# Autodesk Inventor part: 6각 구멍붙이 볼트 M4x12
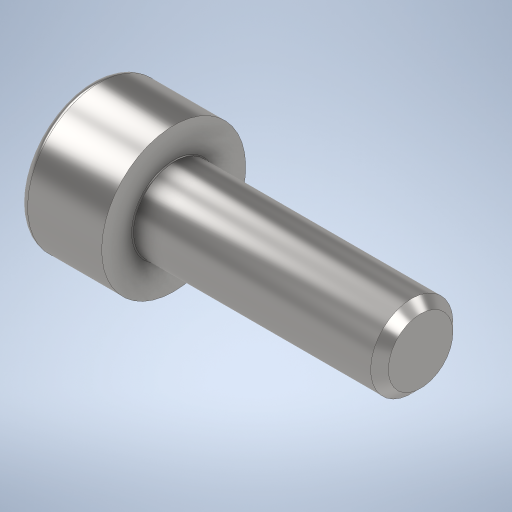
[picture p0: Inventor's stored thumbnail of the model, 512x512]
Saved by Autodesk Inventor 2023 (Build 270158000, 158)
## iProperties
Created: 2026-04
Part Number: 6각 구멍붙이 볼트 M4x12
Material: 강철, 연강
Description: 6각머리 태핑 나사
Document SubType Name: Modeling
Designer: home
Density: 7.85 g/cm^3
Appearance: 기본값
Author: jhkim
Sending System: Autodesk Inventor 2027
Preprocessor: ST-DEVELOPER v20.1
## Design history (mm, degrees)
feature "Solid1"
node "솔리드1"
